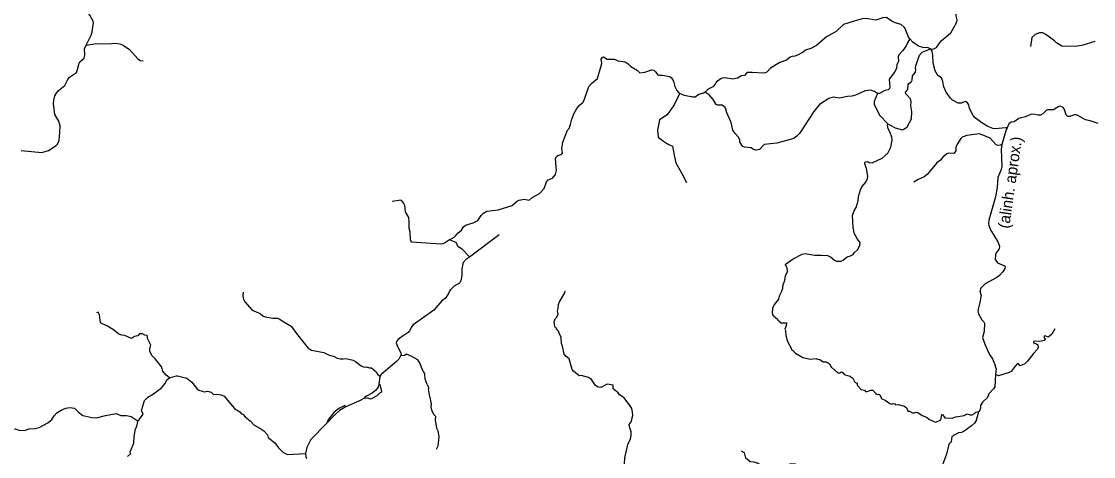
# Model space of a CAD drawing. Extents: x 332 to 501, y 9447 to 9559.
# Drawn here: x 422 to 458.02, y 9497.01 to 9511.64 of the extents above; entities that cross this region are included whole.
import ezdxf

# ---------------------------------------------------------------- set-up
doc = ezdxf.new("R2010")
doc.units = 0
for name, color, linetype in [('Level 31', 7, 'Continuous'), ('Level 4', 7, 'Continuous'), ('Level 5', 7, 'Continuous'), ('Level 6', 7, 'Continuous'), ('Level 7', 7, 'Continuous')]:
    doc.layers.add(name, color=color, linetype=linetype)

msp = doc.modelspace()

# ---------------------------------------------------------------- linework, layer by layer
at = {"layer": 'Level 4'}
for points in [[(437.0509, 9503.7292), (438.0452, 9504.4822)], [(436.3971, 9502.5795), (436.4243, 9502.6286), (436.5544, 9502.7509), (436.7334, 9502.8532), (436.7862, 9502.9636), (436.8102, 9503.1171), (436.8086, 9503.3217), (436.8498, 9503.5465), (436.9534, 9503.66), (437.0509, 9503.7292)], [(456.713, 9501.307), (456.618, 9501.133), (456.53, 9501.047), (456.489, 9501.027), (456.387, 9501.076), (456.358, 9501.057), (456.356, 9501.002), (456.393, 9500.985), (456.396, 9500.956), (456.361, 9500.916), (456.217, 9500.879), (456.016, 9500.89), (455.9999, 9500.8421)], [(455.9999, 9500.8421), (456.106, 9500.801), (456.142, 9500.766), (456.16, 9500.696), (456.139, 9500.627), (455.9999, 9500.4742)], [(455.9999, 9500.4742), (455.8, 9500.22), (455.713, 9500.133), (455.6062, 9500.0893)], [(455.3343, 9500), (455.264, 9499.89), (455.179, 9499.835), (454.823, 9499.725)], [(455.6062, 9500.0893), (455.554, 9500.068), (455.483, 9500.138), (455.446, 9500.131), (455.3343, 9500)], [(454.7281, 9499.7741), (454.6991, 9499.3583), (454.6591, 9499.2863), (454.5041, 9499.1263), (454.4531, 9499.0033), (454.2901, 9498.8443), (454.2201, 9498.7303), (454.2231, 9498.6443), (454.2001, 9498.5693), (454.1607, 9498.5274)], [(454.823, 9499.725), (454.7281, 9499.7741)], [(454.0862, 9498.2438), (454.1373, 9498.4378)], [(454.1373, 9498.4378), (454.1607, 9498.5274)], [(454.0862, 9498.2438), (454.014, 9498.134), (453.919, 9498.044), (453.672, 9497.867), (453.585, 9497.823), (453.476, 9497.808), (453.257, 9497.691), (453.229, 9497.504), (453.16, 9497.431), (453.08, 9497.096), (452.91, 9496.645), (452.893, 9496.419), (452.856, 9496.315), (452.798, 9496.227), (452.4931, 9496)]]:
    msp.add_lwpolyline(points, dxfattribs=at)
at = {"layer": 'Level 5'}
for points in [[(424.1761, 9510.8452), (424.3493, 9511.1855), (424.3781, 9511.2878), (424.4181, 9511.5948), (424.4069, 9511.646), (424.2982, 9511.8474), (424.1611, 9512.0285), (424.1351, 9512.0889), (424.1351, 9512.1688), (424.183, 9512.3223), (424.2886, 9512.4518), (424.3749, 9512.6245), (424.4309, 9512.818), (424.4069, 9512.8947), (424.3189, 9513.0435), (424.2342, 9513.1314), (424.1255, 9513.1682), (423.9512, 9513.1906), (423.8441, 9513.2651)], [(450.5853, 9511.7026), (450.4314, 9511.7349), (450.2909, 9511.7357), (449.9755, 9511.6529), (449.6226, 9511.5351), (449.3728, 9511.3063), (449.0433, 9511.1267), (448.7091, 9510.8386), (448.5218, 9510.7363), (448.3407, 9510.6785), (448.2673, 9510.6051), (448.0768, 9510.5044), (447.9815, 9510.4701), (447.891, 9510.4607), (447.8301, 9510.4357), (447.6974, 9510.335), (447.4819, 9510.2616), (447.168, 9510.0703), (447.0368, 9509.9375), (446.9916, 9509.911), (446.9213, 9509.8993), (446.5481, 9509.9258)], [(451.8439, 9511.0584), (451.804, 9511.1149), (451.69, 9511.4046), (451.6572, 9511.453), (451.5557, 9511.5397), (451.3558, 9511.5928), (451.245, 9511.6459), (451.0607, 9511.7732), (450.9373, 9511.7654), (450.7078, 9511.6881), (450.5853, 9511.7026)], [(452.5363, 9510.722), (452.4613, 9510.7549), (452.288, 9510.7643), (452.1397, 9510.8088), (451.9461, 9510.9478), (451.8439, 9511.0584)], [(423.8473, 9509.9303), (423.8888, 9510.031), (423.94, 9510.2364), (423.968, 9510.2792), (424.1143, 9510.4067), (424.1351, 9510.5139), (424.1207, 9510.717), (424.1761, 9510.8452)], [(424.1761, 9510.8452), (424.4546, 9510.8908), (424.6915, 9510.9008), (424.9122, 9510.8912), (425.1424, 9510.9072), (425.3119, 9510.8928), (425.4206, 9510.8433), (425.6317, 9510.701), (425.9099, 9510.3882), (425.992, 9510.3336), (426.0888, 9510.3164)], [(452.5524, 9510.7098), (452.5363, 9510.722)], [(455.1181, 9508.0604), (455.0721, 9508.069), (454.7067, 9508.0269), (454.6317, 9508.0433), (454.4709, 9508.112), (454.2664, 9508.2307), (454.0352, 9508.4064), (453.9759, 9508.4751), (453.8463, 9508.7179), (453.826, 9508.8397), (453.7885, 9508.9037), (453.7417, 9508.9443), (453.7042, 9508.9505), (453.5839, 9508.8943), (453.4653, 9508.899), (453.281, 9508.9966), (453.2092, 9509.0669), (453.0609, 9509.2652), (452.9891, 9509.4409), (452.9594, 9509.6236), (452.911, 9509.7493), (452.7908, 9509.8289), (452.6924, 9509.9773), (452.6252, 9510.2341), (452.619, 9510.509), (452.5987, 9510.641), (452.5524, 9510.7098)], [(440.1228, 9507.169), (440.1552, 9507.1864), (440.1728, 9507.2216), (440.16, 9507.3543), (440.192, 9507.5846), (440.3487, 9507.9827), (440.4033, 9508.0481), (440.451, 9508.1762), (440.4894, 9508.3585), (440.5598, 9508.5408), (440.6589, 9508.7198), (440.7437, 9508.8286), (440.8556, 9508.9213), (440.902, 9508.9901), (441.0666, 9509.4538), (441.1466, 9509.5593), (441.3513, 9509.7288), (441.5016, 9510.2325), (441.4792, 9510.3716), (441.524, 9510.4419), (441.5543, 9510.4467), (441.6791, 9510.378), (441.9253, 9510.3716), (442.0324, 9510.314), (442.2867, 9510.2788), (442.3842, 9510.2213), (442.4753, 9510.1237), (442.6944, 9509.991), (442.7808, 9509.9159), (442.9486, 9509.9398), (443.1661, 9510.0134), (443.2413, 9510.007), (443.3036, 9509.9526), (443.3757, 9509.8474), (443.4258, 9509.8327)], [(423.1533, 9509.1931), (423.2412, 9509.3131), (423.4587, 9509.4921), (423.5578, 9509.6872), (423.6218, 9509.7704), (423.8473, 9509.9303)], [(443.4258, 9509.8327), (443.5226, 9509.8381), (443.7833, 9509.7863), (443.8438, 9509.7455), (443.9111, 9509.6378), (443.9481, 9509.4499), (444.0151, 9509.3179), (444.0903, 9509.2427), (444.2328, 9509.1793)], [(421.9925, 9507.3063), (422.6832, 9507.2344), (422.9119, 9507.3079), (423.1677, 9507.4667), (423.2134, 9507.5203), (423.2652, 9507.6389), (423.2956, 9507.9108), (423.3004, 9508.1282), (423.2556, 9508.2913), (423.1229, 9508.5088), (423.0828, 9508.8883), (423.0892, 9508.991), (423.1229, 9509.1356), (423.1533, 9509.1931)], [(458.1691, 9508.2095), (457.9068, 9508.3055), (457.7444, 9508.3336), (457.5102, 9508.4734), (457.4415, 9508.4984), (457.3774, 9508.5015), (457.226, 9508.4499), (457.1698, 9508.4437), (457.137, 9508.457), (457.0933, 9508.4976), (457.0355, 9508.7021), (456.9996, 9508.7537), (456.8997, 9508.7943), (456.8513, 9508.7849), (456.6732, 9508.6733), (456.4734, 9508.6717), (456.4234, 9508.6451), (456.3157, 9508.5312), (456.2329, 9508.4929), (456.1439, 9508.4883), (456.0503, 9508.5164), (455.9238, 9508.5242), (455.7271, 9508.4313), (455.5022, 9508.3751), (455.3461, 9508.2713), (455.2539, 9508.2525), (455.1665, 9508.2025), (455.1181, 9508.0604)], [(455.1181, 9508.0604), (455.0759, 9507.9683), (454.9333, 9507.5041)], [(454.9333, 9507.5041), (454.9135, 9507.3437), (454.9338, 9506.7644), (454.9104, 9506.666), (454.8057, 9506.399), (454.7807, 9506.0609), (454.7261, 9505.7478), (454.5013, 9504.9608), (454.4903, 9504.8499), (454.5013, 9504.7828), (454.5591, 9504.6352), (454.7995, 9504.2332), (454.8542, 9504.0911), (454.8433, 9503.9989), (454.7434, 9503.8669), (454.7184, 9503.7967), (454.7168, 9503.6358), (454.7964, 9503.5257), (455.0291, 9503.4242), (455.0447, 9503.4023), (455.0333, 9503.3332)], [(438.7237, 9505.6329), (438.8953, 9505.6658), (439.0631, 9505.6306), (439.1639, 9505.7202), (439.4101, 9505.8561), (439.5565, 9506.0202), (439.6404, 9506.2446), (439.6995, 9506.3134), (439.8418, 9506.3773), (439.947, 9506.4959), (439.9711, 9506.6291), (439.9449, 9507.0223), (439.9808, 9507.1004), (440.025, 9507.1358), (440.1228, 9507.169)], [(434.8787, 9505.4525), (434.8324, 9505.5435), (434.7587, 9505.6306), (434.4536, 9505.5905)], [(436.3763, 9504.3049), (436.5381, 9504.3904), (436.5847, 9504.4314), (436.6663, 9504.5273), (436.783, 9504.6265), (436.8534, 9504.7384), (436.9141, 9504.7976), (437.1796, 9504.8663), (437.3315, 9504.9479), (437.4466, 9505.1206), (437.5265, 9505.1973), (437.6353, 9505.2613), (438.0206, 9505.314), (438.4875, 9505.4531), (438.6673, 9505.6074), (438.7237, 9505.6329)], [(435.0245, 9504.896), (435.0193, 9505.0502), (434.9075, 9505.2364), (434.8787, 9505.4525)], [(436.3763, 9504.3049), (436.209, 9504.1899), (436.1594, 9504.1644), (436.0763, 9504.15), (435.1185, 9504.2171), (435.0849, 9504.2619), (435.0769, 9504.3035), (435.0561, 9504.5689), (435.0305, 9504.684), (435.0245, 9504.896)], [(437.0509, 9503.7292), (436.8038, 9503.9853), (436.6775, 9504.0652), (436.6071, 9504.2139), (436.3763, 9504.3049)], [(455.0333, 9503.3332), (454.9666, 9503.2275), (454.8526, 9503.0987), (454.7699, 9503.0362), (454.3748, 9502.8262), (454.2249, 9502.6653), (454.2059, 9502.5783)], [(429.45, 9502.5425), (429.4421, 9502.4136), (429.4613, 9502.3027), (429.5078, 9502.2156), (429.7562, 9501.94), (430.0265, 9501.8205), (430.1099, 9501.7458), (430.1878, 9501.7062), (430.4468, 9501.6631), (430.6009, 9501.6704), (430.661, 9501.6473), (430.8111, 9501.5377), (431.0618, 9501.3986), (431.2727, 9501.1058), (431.6391, 9500.662), (431.7415, 9500.5891), (432.1551, 9500.5153)], [(436.352, 9502.491), (436.247, 9502.339), (436.127, 9502.249), (435.851, 9501.937), (435.161, 9501.44), (435.118, 9501.388), (435.042, 9501.239), (434.991, 9501.182), (434.763, 9501.024)], [(436.352, 9502.491), (436.3971, 9502.5795)], [(447.5461, 9502.5875), (447.453, 9502.402), (447.438, 9502.303), (447.276, 9502.1), (447.233, 9501.994), (447.219, 9501.848), (447.24, 9501.77), (447.401, 9501.637), (447.414, 9501.599), (447.478, 9501.549), (447.493, 9501.512), (447.699, 9501.509), (447.688, 9501.407), (447.647, 9501.297), (447.671, 9501.252), (447.684, 9501.099), (447.73, 9500.904), (447.89, 9500.596), (447.921, 9500.582), (447.9999, 9500.4878)], [(454.239, 9502.4552), (454.202, 9502.198), (454.128, 9501.92), (454.149, 9501.808), (454.26, 9501.613), (454.333, 9501.544), (454.3539, 9501.5035)], [(454.239, 9502.4552), (454.2059, 9502.5783)], [(454.3539, 9501.5035), (454.34, 9501.215), (454.291, 9501.018), (454.364, 9500.787), (454.5266, 9500.4438)], [(434.763, 9501.024), (434.654, 9500.946), (434.601, 9500.886), (434.585, 9500.835), (434.645, 9500.686), (434.744, 9500.504), (434.76, 9500.442), (434.7358, 9500.3954)], [(432.1551, 9500.5153), (432.3189, 9500.4307), (432.5088, 9500.378), (432.61, 9500.3248), (432.7118, 9500.2964), (432.8111, 9500.2941), (432.9022, 9500.3137), (433.145, 9500.2564), (433.2278, 9500.2132), (433.416, 9500.0604), (433.5196, 9500.0154), (433.5814, 9500.032), (433.6951, 9500.0007), (433.7624, 9500.0008), (433.9142, 9499.8639), (433.9637, 9499.7839), (434.0274, 9499.7323), (434.047, 9499.697)], [(434.7358, 9500.3954), (434.682, 9500.292), (434.604, 9500.205), (434.085, 9499.776), (434.047, 9499.697)], [(435.632, 9499.431), (435.57, 9499.617), (435.557, 9499.793), (435.451, 9499.979), (435.383, 9500.166), (435.321, 9500.264), (435.12, 9500.383), (434.9421, 9500.4596), (434.8672, 9500.4116), (434.7358, 9500.3954)], [(447.9999, 9500.4878), (448.248, 9500.339), (448.507, 9500.293), (448.694, 9500.305), (448.746, 9500.283), (448.824, 9500.276), (448.931, 9500.203), (449.049, 9500.199), (449.142, 9500.132), (449.209, 9500.012), (449.2317, 9500)], [(454.5266, 9500.4438), (454.6178, 9500.3003), (454.7237, 9500.0498)], [(449.2317, 9500), (449.422, 9499.831), (449.491, 9499.825), (449.548, 9499.858), (449.602, 9499.826), (449.645, 9499.775), (449.827, 9499.715), (449.931, 9499.654)], [(454.7363, 9500), (454.7237, 9500.0498)], [(454.7416, 9499.9788), (454.7281, 9499.7741)], [(454.7416, 9499.9788), (454.7363, 9500)], [(425.9664, 9498.2711), (426.092, 9498.443), (426.031, 9498.559), (426.131, 9498.897), (426.246, 9499.016), (426.435, 9499.123), (426.711, 9499.32), (426.829, 9499.465), (426.8891, 9499.5878), (426.9703, 9499.6659)], [(426.9703, 9499.6659), (427.2152, 9499.7253)], [(427.2152, 9499.7253), (427.246, 9499.731), (427.5582, 9499.6541)], [(427.5582, 9499.6541), (427.73, 9499.518), (427.93, 9499.261), (428.14, 9499.186), (428.25, 9499.215), (428.371, 9499.174), (428.457, 9499.099), (428.581, 9499.106), (428.707, 9499.086), (428.81, 9499.039), (429.156, 9498.628), (429.2039, 9498.5916)], [(434.047, 9499.697), (434.0041, 9499.4421)], [(449.931, 9499.654), (450, 9499.52), (450.074, 9499.48), (450.077, 9499.417), (450.214, 9499.273), (450.324, 9499.241), (450.357, 9499.204), (450.411, 9499.203), (450.531, 9499.245), (450.607, 9499.246), (450.701, 9499.129), (450.747, 9499.097), (450.789, 9499.108), (450.823, 9499.096), (450.907, 9498.959), (451.013, 9498.912), (451.169, 9498.801), (451.238, 9498.779), (451.291, 9498.794), (451.337, 9498.786), (451.361, 9498.756), (451.459, 9498.763), (451.6619, 9498.713)], [(433.531, 9498.978), (433.626, 9498.987), (433.713, 9498.959), (433.772, 9498.966), (433.949, 9499.065), (434.045, 9499.152), (434.108, 9499.185), (434.063, 9499.405), (434.0041, 9499.4421)], [(434.0041, 9499.4421), (433.983, 9499.347), (433.894, 9499.236), (433.788, 9499.148), (433.589, 9499.045), (433.541, 9499.008), (433.531, 9498.978)], [(435.632, 9499.431), (435.6738, 9499.3374)], [(435.6738, 9499.3374), (435.682, 9499.291)], [(435.722, 9499.022), (435.682, 9499.291)], [(433.531, 9498.978), (433.354, 9498.882), (432.895, 9498.682)], [(435.745, 9498.886), (435.769, 9498.783), (435.759, 9498.684), (435.776, 9498.587), (435.839, 9498.44), (435.909, 9498.374), (435.903, 9498.247), (435.944, 9497.967), (435.988, 9497.884), (436.029, 9497.693), (435.99, 9497.364), (435.931, 9497.247)], [(421.595, 9497.869), (421.644, 9497.92), (421.794, 9497.941), (421.919, 9497.896), (422.101, 9497.885), (422.262, 9497.949), (422.467, 9497.955), (422.597, 9497.995), (422.894, 9498.145), (423.019, 9498.264), (423.1, 9498.385), (423.196, 9498.479), (423.339, 9498.57), (423.495, 9498.638), (423.633, 9498.661), (423.782, 9498.639), (423.9222, 9498.508)], [(423.9222, 9498.508), (424.06, 9498.39), (424.366, 9498.322), (424.522, 9498.312), (424.827, 9498.397), (425.182, 9498.459), (425.346, 9498.395), (425.534, 9498.389), (425.692, 9498.364), (425.854, 9498.253), (425.91, 9498.192)], [(429.2039, 9498.5916), (429.2754, 9498.5594), (429.3535, 9498.5074), (429.3993, 9498.4491), (429.4402, 9498.4355), (429.517, 9498.3488), (429.6855, 9498.2125), (429.8205, 9498.0664), (430.0143, 9497.9716), (430.1432, 9497.8774), (430.2671, 9497.7486), (430.2894, 9497.6569), (430.5198, 9497.4736), (430.6412, 9497.3076), (430.7824, 9497.1664), (430.9361, 9497.0797), (431.549, 9497.12)], [(432.895, 9498.682), (432.868, 9498.726), (432.796, 9498.695), (432.66, 9498.626), (432.5, 9498.496), (432.299, 9498.234), (432.2621, 9498.1324)], [(432.895, 9498.682), (432.692, 9498.561), (432.523, 9498.408), (432.2621, 9498.1324)], [(451.6619, 9498.713), (451.74, 9498.644), (451.78, 9498.538), (451.832, 9498.541), (451.935, 9498.488), (451.9999, 9498.4877)], [(451.9999, 9498.4877), (452.063, 9498.51), (452.12, 9498.495), (452.261, 9498.391), (452.407, 9498.339), (452.501, 9498.259), (452.707, 9498.174), (452.801, 9498.2), (452.889, 9498.246), (452.918, 9498.429), (452.945, 9498.429), (453.024, 9498.32), (453.273, 9498.3), (453.396, 9498.348), (453.674, 9498.393), (453.774, 9498.453), (453.874, 9498.42), (453.94, 9498.422), (454.013, 9498.457), (454.059, 9498.506), (454.1154, 9498.5228)], [(454.1154, 9498.5228), (454.1607, 9498.5274)], [(425.91, 9498.192), (425.9664, 9498.2711)], [(432.2621, 9498.1324), (431.725, 9497.591), (431.587, 9497.316), (431.549, 9497.12)], [(431.549, 9497.12), (431.551, 9497.011), (431.575, 9496.947)], [(447.9999, 9496.7707), (447.8203, 9496.7635), (447.668, 9496.6858), (447.5254, 9496.6534), (447.344, 9496.54), (447.2533, 9496.5043), (447.0881, 9496.5724), (446.7155, 9496.7927), (446.6184, 9496.8283), (446.4855, 9496.8348), (446.3398, 9496.9644), (446.2912, 9497.1393), (446.1907, 9497.1944)]]:
    msp.add_lwpolyline(points, dxfattribs=at)
at = {"layer": 'Level 6'}
for points in [[(452.5524, 9510.7098), (452.6489, 9510.726), (452.7422, 9510.7647), (452.901, 9510.9852), (453.2206, 9511.2602), (453.3654, 9511.5174)], [(446.5481, 9509.9258), (446.3887, 9509.9208), (446.354, 9509.9029), (446.2875, 9509.8265), (446.1902, 9509.8096), (446.0523, 9509.7332), (445.8994, 9509.7014), (445.6194, 9509.7481), (445.5092, 9509.7273), (445.3395, 9509.5983), (445.3048, 9509.5328), (445.2264, 9509.4425), (445.0726, 9509.3642), (444.9681, 9509.2699)], [(444.0903, 9509.2427), (444.0986, 9509.2189), (444.0948, 9509.1896), (443.9294, 9508.8384), (443.6981, 9508.5065), (443.4366, 9508.3355), (443.3662, 9507.9836), (443.3964, 9507.7523), (443.5674, 9507.6215), (443.7081, 9507.531), (443.8691, 9507.4506), (443.9294, 9507.1489), (443.9897, 9506.8874), (444.1909, 9506.5253), (444.3417, 9506.2236)], [(444.9681, 9509.2699), (444.9356, 9509.246), (444.7549, 9509.1905), (444.6298, 9509.0943), (444.5612, 9509.0936)], [(444.2328, 9509.1793), (444.483, 9509.1164)], [(444.5612, 9509.0936), (444.483, 9509.1164)], [(440.175, 9500.727), (440.141, 9500.812), (440.133, 9501.029), (440.076, 9501.123), (440.046, 9501.233), (439.977, 9501.293), (439.982, 9501.331), (439.943, 9501.339), (439.92, 9501.391), (439.894, 9501.547), (439.934, 9501.648), (439.989, 9501.697), (440.032, 9501.801), (440.007, 9501.9), (440.036, 9501.994), (440.049, 9502.126), (440.081, 9502.212), (440.252, 9502.521), (440.2687, 9502.5825)], [(426.32, 9500.551), (426.318, 9500.645), (426.349, 9500.76), (426.246, 9500.955), (426.224, 9501.079), (426.143, 9501.098), (426.07, 9501.137), (425.967, 9501.136), (425.907, 9501.073), (425.799, 9501.05), (425.704, 9500.988), (425.478, 9501.082), (425.37, 9501.093), (425.273, 9501.124), (425.096, 9501.269), (424.893, 9501.397), (424.656, 9501.51), (424.623, 9501.778), (424.584, 9501.868), (424.525, 9501.845)], [(442.3707, 9497.4165), (442.466, 9497.611), (442.488, 9497.723), (442.485, 9497.845), (442.438, 9497.982), (442.42, 9498.095), (442.484, 9498.186), (442.541, 9498.389), (442.534, 9498.51), (442.507, 9498.627), (442.443, 9498.73), (442.247, 9498.99), (442.092, 9499.09), (442.051, 9499.154), (441.883, 9499.291), (441.88, 9499.416), (441.678, 9499.449), (441.471, 9499.332), (441.377, 9499.351), (441.284, 9499.407), (441.156, 9499.607), (441.054, 9499.669), (440.81, 9499.738), (440.736, 9499.733), (440.552, 9499.886), (440.505, 9499.937), (440.397, 9500.3), (440.296, 9500.38), (440.231, 9500.458), (440.175, 9500.727)], [(426.9703, 9499.6659), (426.853, 9499.756), (426.754, 9499.884), (426.715, 9500.021), (426.504, 9500.292), (426.39, 9500.404), (426.32, 9500.551)], [(435.722, 9499.022), (435.745, 9498.886)], [(425.562, 9497.011), (425.665, 9497.102), (425.659, 9497.172), (425.782, 9497.464), (425.793, 9497.683), (425.837, 9497.95), (425.877, 9498.027), (425.91, 9498.192)], [(442.262, 9496.767), (442.272, 9496.975), (442.3707, 9497.4165)]]:
    msp.add_lwpolyline(points, dxfattribs=at)
at = {"layer": 'Level 7'}
for points in [[(454.9962, 9513.6169), (454.8554, 9513.3502), (454.6599, 9513.0969), (454.5408, 9512.9767), (454.4187, 9512.9082), (454.3005, 9512.9042), (454.1715, 9512.8635), (453.98, 9512.7145), (453.8817, 9512.6122), (453.6723, 9512.2498), (453.4907, 9512.0661), (453.4401, 9511.9906), (453.3954, 9511.8655), (453.3984, 9511.7801), (453.4232, 9511.6898), (453.4182, 9511.6272), (453.3654, 9511.5174)], [(451.8439, 9511.0584), (451.7777, 9510.9508), (451.7211, 9510.8178), (451.6129, 9510.6648), (451.472, 9510.5149), (451.4522, 9510.4553), (451.463, 9510.3104), (451.4055, 9510.1823), (451.3936, 9510.0611), (451.3351, 9509.937), (451.1485, 9509.6967), (451.1704, 9509.4335), (451.1575, 9509.3928), (451.1188, 9509.3481), (451.0007, 9509.3193), (450.83, 9509.218), (450.7546, 9509.215)], [(458.0579, 9510.9667), (457.6222, 9510.8346), (457.388, 9510.7969), (456.9554, 9510.8087), (456.7678, 9510.9249), (456.7072, 9510.9924), (456.4164, 9511.2049), (456.3082, 9511.2536), (456.207, 9511.2606), (456.0522, 9511.203), (455.946, 9511.1027), (455.8944, 9510.7968)], [(451.102, 9508.1982), (451.3521, 9508.0691), (451.6032, 9507.9976), (451.6707, 9508.0264), (451.757, 9508.0949), (451.897, 9508.363), (451.9099, 9508.6004), (451.8821, 9508.81), (451.896, 9508.9391), (451.8712, 9509.0424), (451.7163, 9509.2043), (451.7044, 9509.2659), (451.7779, 9509.3523), (451.7947, 9509.5182), (451.8146, 9509.5529), (451.9029, 9509.6235), (451.9257, 9509.6682), (451.9386, 9509.8083), (452.0418, 9509.9314), (452.0498, 9510.0317), (452.0359, 9510.0873), (452.0498, 9510.1509), (452.169, 9510.5075), (452.2623, 9510.6117), (452.5363, 9510.722)], [(449.2689, 9509.0988), (449.126, 9509.0492), (448.8094, 9508.8486), (448.6208, 9508.6142), (448.1396, 9507.8803), (448.0533, 9507.783), (447.953, 9507.7026), (447.3824, 9507.5545), (446.9566, 9507.5008), (446.7929, 9507.3419), (446.7522, 9507.3211), (446.6628, 9507.3091), (446.5944, 9507.3349), (446.514, 9507.3915), (446.2877, 9507.4164), (446.2371, 9507.4412), (446.2014, 9507.48), (446.1398, 9507.5942), (446.1388, 9507.6548), (446.0902, 9507.7511), (445.9731, 9507.8803), (445.9046, 9507.9845), (445.8431, 9508.2487), (445.6982, 9508.5645), (445.6684, 9508.6956), (445.6396, 9508.7472), (445.5366, 9508.8221), (445.3854, 9508.8257), (445.3348, 9508.8545), (445.2434, 9509.0124), (445.1015, 9509.1703), (444.9681, 9509.2699)], [(450.7546, 9509.215), (450.6534, 9509.2865), (450.5193, 9509.3302), (450.3466, 9509.3113), (450.0251, 9509.1623), (449.8991, 9509.1345), (449.7542, 9509.1236), (449.4843, 9509.067), (449.2689, 9509.0988)], [(450.7546, 9509.215), (450.6474, 9508.9509), (450.6454, 9508.8605), (450.8251, 9508.4892), (451.102, 9508.1982)], [(450.1801, 9504.2061), (450.0908, 9504.3203), (449.9915, 9504.507), (449.9439, 9504.6997), (449.9241, 9505.1148), (449.9638, 9505.2528), (450.0392, 9505.3849), (450.1117, 9505.6133), (450.1266, 9505.7533), (450.1832, 9505.9817), (450.2378, 9506.084), (450.3698, 9506.2398), (450.4244, 9506.364), (450.4303, 9506.4375), (450.3856, 9506.7036), (450.333, 9506.8566), (450.3379, 9506.8953), (450.3597, 9506.9181), (450.4183, 9506.9291), (450.4769, 9506.9052), (450.5811, 9506.8923), (450.9205, 9507.0492), (451.1081, 9507.215), (451.2024, 9507.4107), (451.25, 9507.6659), (451.246, 9507.7523), (451.1884, 9507.9053), (451.1189, 9508.0294), (451.0931, 9508.1535), (451.102, 9508.1982)], [(454.9333, 9507.5041), (454.8839, 9507.4785), (454.7985, 9507.4705), (454.7469, 9507.4914), (454.5455, 9507.7138), (454.2795, 9507.8319), (454.1762, 9507.8627), (453.7624, 9507.8031), (453.6066, 9507.7465), (453.5619, 9507.7058), (453.4289, 9507.4893), (453.3932, 9507.4108), (453.3942, 9507.2967), (453.3297, 9507.2153), (453.2999, 9507.2013), (453.156, 9507.2123), (453.0885, 9507.1895), (452.9595, 9507.0832), (452.8791, 9506.9819), (452.7561, 9506.8836), (452.4306, 9506.4913), (452.3264, 9506.4188), (452.1229, 9506.3334), (451.98, 9506.2341)], [(447.6537, 9503.4739), (447.9217, 9503.6595), (448.2323, 9503.8155), (448.3246, 9503.8393), (448.6561, 9503.7818), (448.8833, 9503.7858), (449.0798, 9503.7679), (449.18, 9503.7282), (449.3199, 9503.6139), (449.3874, 9503.5861), (449.5353, 9503.5851), (449.6137, 9503.6228), (449.7387, 9503.7232), (449.8558, 9503.7569), (449.9437, 9503.8039), (449.9785, 9503.8635), (450.1006, 9503.9757), (450.1652, 9504.1207), (450.1801, 9504.2061)], [(447.5461, 9502.5875), (447.5793, 9502.6712), (447.5882, 9502.8023), (447.6418, 9502.9294), (447.6666, 9503.0913), (447.7321, 9503.2374), (447.7222, 9503.3587), (447.6944, 9503.4282), (447.6537, 9503.4739)]]:
    msp.add_lwpolyline(points, dxfattribs=at)

# ---------------------------------------------------------------- texts
at = {"layer": 'Level 31'}
msp.add_text('(alinh. aprox.)', height=0.38, rotation=81.85547, dxfattribs=at).set_placement((455.1815, 9504.666))

doc.saveas('drawing.dxf')
